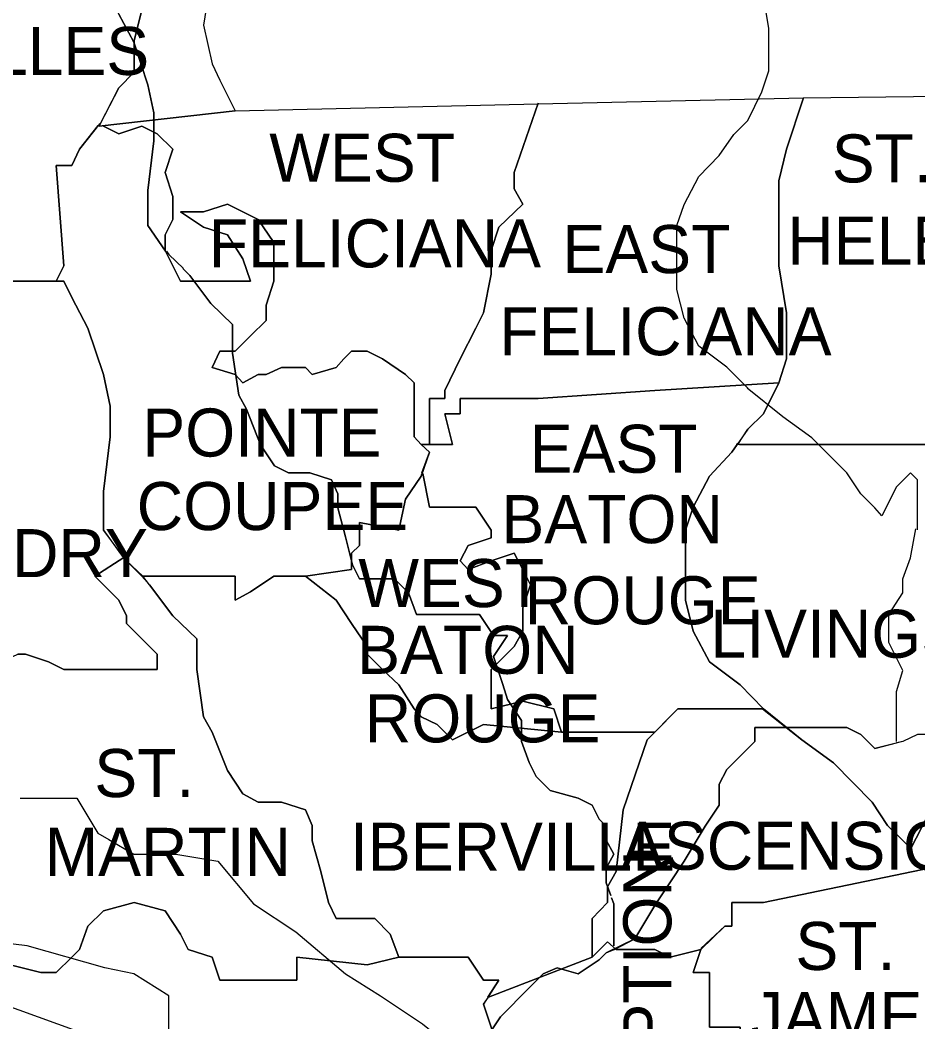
# Model space of a CAD drawing. Extents: x 0.19 to 2.82, y 0.04 to 1.79.
# Drawn here: x 2.3673 to 2.4634, y 1.4536 to 1.5609 of the extents above; entities that cross this region are included whole.
import ezdxf

# ---------------------------------------------------------------- set-up
doc = ezdxf.new("R2010")
doc.units = 0
for name, color, linetype in [('Dist02', 7, 'Continuous'), ('Dist03', 7, 'Continuous'), ('Dist61', 7, 'Continuous'), ('Dist62', 7, 'Continuous'), ('Standard Info', 7, 'Continuous')]:
    doc.layers.add(name, color=color, linetype=linetype)

msp = doc.modelspace()

# ---------------------------------------------------------------- linework, layer by layer
at = {"layer": 'Dist02'}
for points in [[(2.47174, 1.48442), (2.46715, 1.48442), (2.46565, 1.48292), (2.4649, 1.48442), (2.4634, 1.48442), (2.46182, 1.48367), (2.45882, 1.48292), (2.45732, 1.48442), (2.45582, 1.48517), (2.45357, 1.48517), (2.44599, 1.48517), (2.44599, 1.48367), (2.44299, 1.48067), (2.44215, 1.47908), (2.44215, 1.47683), (2.44065, 1.47458), (2.4384, 1.47083), (2.4369, 1.4685)], [(2.4369, 1.4685), (2.4354, 1.46625), (2.43315, 1.4625), (2.43007, 1.461), (2.42932, 1.46025), (2.42707, 1.45875), (2.42482, 1.45942), (2.42332, 1.45875), (2.42182, 1.45725), (2.41874, 1.45417), (2.41724, 1.45192), (2.41799, 1.44967), (2.41799, 1.44817), (2.42032, 1.44508), (2.42182, 1.44358), (2.42182, 1.44208), (2.42099, 1.44133), (2.41949, 1.43983), (2.41799, 1.43825), (2.41574, 1.43492)]]:
    msp.add_lwpolyline(points, dxfattribs=at)
at = {"layer": 'Dist03'}
for points in [[(2.3829, 1.53617), (2.38099, 1.53892), (2.38099, 1.54267), (2.38165, 1.548), (2.38165, 1.551), (2.38099, 1.554), (2.37949, 1.55858), (2.3779, 1.56158), (2.37715, 1.56308)], [(2.40974, 1.49725), (2.4089, 1.49958), (2.4074, 1.50108), (2.40365, 1.50108), (2.4029, 1.50258), (2.40215, 1.50558), (2.40132, 1.50867), (2.40132, 1.51017), (2.40065, 1.51167), (2.39832, 1.51242), (2.39607, 1.51242), (2.39457, 1.51317), (2.39307, 1.51542), (2.39157, 1.51925), (2.39074, 1.52075), (2.39007, 1.52525), (2.39007, 1.52833), (2.38774, 1.53058), (2.38549, 1.53358), (2.38474, 1.53433)], [(2.41899, 1.48975), (2.41799, 1.49275), (2.41949, 1.495), (2.41799, 1.495), (2.41649, 1.49725), (2.40974, 1.49725)], [(2.43057, 1.46717), (2.43007, 1.4685), (2.43007, 1.47008), (2.4309, 1.47158), (2.43007, 1.47308), (2.43007, 1.47458), (2.42932, 1.47533), (2.42857, 1.47683), (2.42707, 1.47758), (2.42407, 1.47842), (2.42257, 1.47992), (2.42182, 1.48142), (2.42099, 1.48367), (2.42099, 1.48592), (2.41949, 1.48817), (2.41899, 1.48975)], [(2.36732, 1.47758), (2.3734, 1.47758), (2.37565, 1.47383), (2.37682, 1.47317)], [(2.37682, 1.47317), (2.37949, 1.47158), (2.38399, 1.47158), (2.38849, 1.47083), (2.39232, 1.46625), (2.39682, 1.46325), (2.40215, 1.45875), (2.4059, 1.45642), (2.4104, 1.45342), (2.41499, 1.44967), (2.41649, 1.44817), (2.41724, 1.44358), (2.41499, 1.44133), (2.41424, 1.43675), (2.41574, 1.435)], [(2.4309, 1.46175), (2.4309, 1.46325), (2.4309, 1.46475), (2.4309, 1.46625), (2.43065, 1.46692)], [(2.36049, 1.45725), (2.36507, 1.45567), (2.3734, 1.45267), (2.37865, 1.45117), (2.38015, 1.45117), (2.38324, 1.45267), (2.38324, 1.45642), (2.37949, 1.45875), (2.3764, 1.45942), (2.36807, 1.46175), (2.36482, 1.46217)], [(2.41574, 1.435), (2.41799, 1.43825), (2.41949, 1.43983), (2.42099, 1.44133), (2.42182, 1.44208), (2.42182, 1.44358), (2.42032, 1.44508), (2.41799, 1.44817), (2.41799, 1.44967), (2.41724, 1.45192), (2.41874, 1.45417), (2.42182, 1.45725), (2.42332, 1.45875), (2.42482, 1.45942), (2.42707, 1.45875), (2.42932, 1.46025), (2.43007, 1.461), (2.43099, 1.46142)]]:
    msp.add_lwpolyline(points, dxfattribs=at)
at = {"layer": 'Dist61'}
for points in [[(2.44674, 1.55325), (2.44749, 1.5555), (2.44749, 1.56008), (2.44674, 1.56458), (2.44674, 1.56983), (2.44674, 1.57292), (2.44749, 1.57592), (2.44915, 1.581)], [(2.37715, 1.56308), (2.3779, 1.56158), (2.37949, 1.55858), (2.38099, 1.554), (2.38165, 1.551), (2.38165, 1.548), (2.38099, 1.54267), (2.38099, 1.53892), (2.3829, 1.53617)], [(2.44524, 1.5215), (2.44299, 1.52375), (2.43999, 1.526), (2.4384, 1.529), (2.43765, 1.53208), (2.43765, 1.53508), (2.43765, 1.53892), (2.4384, 1.54117), (2.43999, 1.54417), (2.44215, 1.54642), (2.44374, 1.54867), (2.44524, 1.55017), (2.44674, 1.55325)], [(2.38299, 1.53617), (2.38324, 1.53583), (2.38482, 1.53433)], [(2.38474, 1.53433), (2.38549, 1.53358), (2.38774, 1.53058), (2.39007, 1.52833), (2.39007, 1.52525), (2.39074, 1.52075), (2.39157, 1.51925), (2.39307, 1.51542), (2.39457, 1.51317), (2.39607, 1.51242), (2.39832, 1.51242), (2.40065, 1.51167), (2.40132, 1.51017), (2.40132, 1.50867), (2.40215, 1.50558), (2.4029, 1.50258), (2.40365, 1.50108), (2.4074, 1.50108), (2.4089, 1.49958), (2.40974, 1.49725)], [(2.4634, 1.50633), (2.4634, 1.51167), (2.46265, 1.51242), (2.46115, 1.51092), (2.45957, 1.50783), (2.45882, 1.50867), (2.45732, 1.51017), (2.45582, 1.51242), (2.45207, 1.51617), (2.44899, 1.51842), (2.44515, 1.5215)], [(2.46115, 1.48367), (2.46115, 1.48667), (2.46115, 1.489), (2.46182, 1.49125), (2.46032, 1.49425), (2.46032, 1.49575), (2.46032, 1.49725), (2.46182, 1.49958), (2.46182, 1.50108), (2.46265, 1.50333), (2.46324, 1.50642)], [(2.40974, 1.49725), (2.41649, 1.49725), (2.41799, 1.495), (2.41949, 1.495), (2.41799, 1.49275), (2.41899, 1.48975)], [(2.41899, 1.48975), (2.41949, 1.48817), (2.42099, 1.48592), (2.42099, 1.48367), (2.42182, 1.48142), (2.42257, 1.47992), (2.42407, 1.47842), (2.42707, 1.47758), (2.42857, 1.47683), (2.42932, 1.47533), (2.43007, 1.47458), (2.43007, 1.47308), (2.4309, 1.47158), (2.43007, 1.47008), (2.43007, 1.4685), (2.43057, 1.46717)], [(2.44524, 1.48292), (2.44599, 1.48367), (2.44599, 1.48517), (2.45357, 1.48517), (2.45582, 1.48517), (2.45732, 1.48442), (2.45882, 1.48292), (2.46115, 1.4835)], [(2.4309, 1.46133), (2.43315, 1.4625), (2.4354, 1.46625), (2.4369, 1.4685), (2.4384, 1.47083), (2.44065, 1.47458), (2.44215, 1.47683), (2.44215, 1.47908), (2.44299, 1.48067), (2.44524, 1.48292)], [(2.43065, 1.46692), (2.4309, 1.46625), (2.4309, 1.46475), (2.4309, 1.46325), (2.4309, 1.46175)]]:
    msp.add_lwpolyline(points, dxfattribs=at)
at = {"layer": 'Dist62'}
for points in [[(2.44674, 1.55325), (2.44749, 1.5555), (2.44749, 1.56008), (2.44674, 1.56458), (2.44674, 1.56983), (2.44674, 1.57292), (2.44749, 1.57592), (2.44915, 1.581)], [(2.44524, 1.5215), (2.44299, 1.52375), (2.43999, 1.526), (2.4384, 1.529), (2.43765, 1.53208), (2.43765, 1.53508), (2.43765, 1.53892), (2.4384, 1.54117), (2.43999, 1.54417), (2.44215, 1.54642), (2.44374, 1.54867), (2.44524, 1.55017), (2.44674, 1.55325)], [(2.4634, 1.50633), (2.4634, 1.51167), (2.46265, 1.51242), (2.46115, 1.51092), (2.45957, 1.50783), (2.45882, 1.50867), (2.45732, 1.51017), (2.45582, 1.51242), (2.45207, 1.51617), (2.44899, 1.51842), (2.44515, 1.5215)], [(2.46115, 1.48367), (2.46115, 1.48667), (2.46115, 1.489), (2.46182, 1.49125), (2.46032, 1.49425), (2.46032, 1.49575), (2.46032, 1.49725), (2.46182, 1.49958), (2.46182, 1.50108), (2.46265, 1.50333), (2.46324, 1.50642)], [(2.47174, 1.48442), (2.46715, 1.48442), (2.46565, 1.48292), (2.4649, 1.48442), (2.4634, 1.48442), (2.46182, 1.48367), (2.46115, 1.4835)]]:
    msp.add_lwpolyline(points, dxfattribs=at)
at = {"layer": 'Standard Info'}
for p, q in [((2.4228, 1.55204), (2.4228, 1.55195)), ((2.45121, 1.55259), (2.47101, 1.55286)), ((2.37201, 1.53297), (2.37119, 1.53297)), ((2.38045, 1.50135), (2.38035, 1.50135))]:
    msp.add_line(p, q, dxfattribs=at)
for points in [[(2.40685, 1.61694), (2.40446, 1.61281), (2.40281, 1.6086), (2.40281, 1.60447), (2.39951, 1.60117), (2.39695, 1.59613), (2.39695, 1.58779), (2.39612, 1.58449), (2.39447, 1.58119), (2.39365, 1.57862), (2.39117, 1.5745), (2.38952, 1.57285), (2.38787, 1.56625), (2.38695, 1.56038), (2.38787, 1.55626), (2.3887, 1.55451), (2.39035, 1.55121)], [(2.35111, 1.57908), (2.35295, 1.57789), (2.3546, 1.57532), (2.35542, 1.57367), (2.35707, 1.57202), (2.3579, 1.57037), (2.35955, 1.56955), (2.3612, 1.5712), (2.36037, 1.57285), (2.36202, 1.5745), (2.36624, 1.5745), (2.36871, 1.5712), (2.37119, 1.56863), (2.37531, 1.56698), (2.37788, 1.56698), (2.37953, 1.56625), (2.38118, 1.56451), (2.38035, 1.56203), (2.37953, 1.55873), (2.37953, 1.55534), (2.37788, 1.55369), (2.37586, 1.54975)], [(2.37577, 1.54956), (2.37788, 1.55369), (2.37953, 1.55534), (2.37953, 1.55873), (2.38035, 1.56203), (2.38118, 1.56451), (2.37953, 1.56625), (2.37788, 1.56698), (2.37531, 1.56698), (2.37119, 1.56863), (2.36871, 1.5712), (2.36798, 1.57211)], [(2.4228, 1.55204), (2.42023, 1.54461), (2.42023, 1.54287), (2.42115, 1.54122), (2.41858, 1.53875), (2.41775, 1.53627), (2.41775, 1.53371), (2.41693, 1.52958), (2.4161, 1.52793), (2.41445, 1.52463), (2.4128, 1.52124), (2.4128, 1.52041), (2.41115, 1.52041), (2.41115, 1.51794), (2.41115, 1.51546)], [(2.41115, 1.51546), (2.41115, 1.51794), (2.41115, 1.52041), (2.4128, 1.52041), (2.4128, 1.52124), (2.41445, 1.52463), (2.4161, 1.52793), (2.41693, 1.52958), (2.41775, 1.53371), (2.41775, 1.53627), (2.41858, 1.53875), (2.42115, 1.54122), (2.42023, 1.54287), (2.42023, 1.54461), (2.4228, 1.55204)], [(2.4228, 1.55195), (2.45121, 1.55259)], [(2.45121, 1.55259), (2.44938, 1.54709), (2.44855, 1.5437), (2.44855, 1.5404), (2.44855, 1.53462), (2.44938, 1.52958), (2.44938, 1.52463), (2.44855, 1.52206)], [(2.44855, 1.52206), (2.44938, 1.52463), (2.44938, 1.52958), (2.44855, 1.53462), (2.44855, 1.5404), (2.44855, 1.5437), (2.44938, 1.54709), (2.45121, 1.55259)], [(2.39035, 1.55121), (2.37577, 1.54956)], [(2.37577, 1.54956), (2.39035, 1.55121)], [(2.39035, 1.55121), (2.4228, 1.55195)], [(2.37586, 1.54984), (2.37366, 1.54709), (2.37284, 1.54535), (2.37119, 1.54535)], [(2.37119, 1.54535), (2.37284, 1.54535), (2.37366, 1.54709), (2.37568, 1.54966)], [(2.38365, 1.54205), (2.38283, 1.54461), (2.38365, 1.54709), (2.382, 1.54874), (2.38035, 1.54956), (2.37788, 1.54874), (2.37623, 1.54956)], [(2.37623, 1.54956), (2.37788, 1.54874), (2.38035, 1.54956), (2.382, 1.54874), (2.38365, 1.54709), (2.38283, 1.54461), (2.38365, 1.54205)], [(2.37119, 1.54535), (2.37201, 1.53462), (2.37119, 1.53297)], [(2.37119, 1.53297), (2.37201, 1.53462), (2.37119, 1.54535)], [(2.37119, 1.53297), (2.33709, 1.53297), (2.33709, 1.53792), (2.33544, 1.53957), (2.33379, 1.54122), (2.33379, 1.5437)], [(2.38448, 1.5404), (2.38695, 1.53875), (2.38952, 1.53792), (2.39117, 1.53536), (2.392, 1.53297), (2.39035, 1.53297), (2.38622, 1.53297), (2.38448, 1.53297), (2.38365, 1.53462), (2.38283, 1.53627), (2.38283, 1.53792), (2.38365, 1.53957), (2.38365, 1.54205)], [(2.38365, 1.54205), (2.38365, 1.53957), (2.38283, 1.53792), (2.38283, 1.53627), (2.38365, 1.53462), (2.38448, 1.53297), (2.38622, 1.53297), (2.39035, 1.53297), (2.392, 1.53297), (2.39117, 1.53536), (2.38952, 1.53792), (2.38695, 1.53875), (2.38448, 1.5404)], [(2.41024, 1.51546), (2.4095, 1.51629), (2.4095, 1.51876), (2.4095, 1.52206), (2.40859, 1.52298), (2.40611, 1.52463), (2.40446, 1.52546), (2.40281, 1.52546), (2.40199, 1.52463), (2.40116, 1.52371), (2.3986, 1.52298), (2.39786, 1.52371), (2.3953, 1.52371), (2.39365, 1.52298), (2.39282, 1.52298), (2.39117, 1.52206), (2.39035, 1.52298), (2.38787, 1.52371), (2.3887, 1.52546), (2.39035, 1.52546), (2.392, 1.52711), (2.39365, 1.52876), (2.39365, 1.53041), (2.39447, 1.53297), (2.39447, 1.5371), (2.39282, 1.53957), (2.38952, 1.54122), (2.38695, 1.5404), (2.38448, 1.5404)], [(2.38448, 1.5404), (2.38695, 1.5404), (2.38952, 1.54122), (2.39282, 1.53957), (2.39447, 1.5371), (2.39447, 1.53297), (2.39365, 1.53041), (2.39365, 1.52876), (2.392, 1.52711), (2.39035, 1.52546), (2.3887, 1.52546), (2.38787, 1.52371), (2.39035, 1.52298), (2.39117, 1.52206), (2.39282, 1.52298), (2.39365, 1.52298), (2.3953, 1.52371), (2.39786, 1.52371), (2.3986, 1.52298), (2.40116, 1.52371), (2.40199, 1.52463), (2.40281, 1.52546), (2.40446, 1.52546), (2.40611, 1.52463), (2.40859, 1.52298), (2.4095, 1.52206), (2.4095, 1.51876), (2.4095, 1.51629), (2.41024, 1.51546), (2.41115, 1.51464), (2.41024, 1.51207), (2.40859, 1.5096), (2.40785, 1.5063), (2.40364, 1.50712), (2.40364, 1.50465), (2.40281, 1.50382), (2.40281, 1.50208), (2.39786, 1.50135)], [(2.33874, 1.53297), (2.37201, 1.53297)], [(2.37201, 1.53297), (2.37284, 1.53123), (2.37458, 1.52793), (2.37623, 1.52298), (2.37696, 1.51959), (2.37696, 1.51629), (2.37623, 1.51042), (2.37623, 1.5063), (2.37834, 1.50336)], [(2.38035, 1.50135), (2.3787, 1.503), (2.37623, 1.5063), (2.37623, 1.51042), (2.37696, 1.51629), (2.37696, 1.51959), (2.37623, 1.52298), (2.37458, 1.52793), (2.37284, 1.53123), (2.37201, 1.53297)], [(2.41024, 1.51546), (2.41363, 1.51546), (2.4128, 1.51876), (2.41445, 1.51876), (2.41445, 1.52041), (2.4228, 1.52041), (2.43526, 1.52124), (2.44855, 1.52206)], [(2.44855, 1.52206), (2.43526, 1.52124), (2.4228, 1.52041), (2.41445, 1.52041), (2.41445, 1.51876), (2.4128, 1.51876), (2.41363, 1.51546), (2.41115, 1.51546)], [(2.44855, 1.52206), (2.4469, 1.51876), (2.44525, 1.51711), (2.44351, 1.51464), (2.44113, 1.51207), (2.43939, 1.50877), (2.43856, 1.5063), (2.43856, 1.50208), (2.43856, 1.49878), (2.43939, 1.49548), (2.44113, 1.49218), (2.44443, 1.48971), (2.4469, 1.48714)], [(2.44415, 1.51546), (2.44525, 1.51711), (2.4469, 1.51876), (2.44855, 1.52206)], [(2.4712, 1.51684), (2.4657, 1.51546), (2.44397, 1.51546)], [(2.44434, 1.51546), (2.46606, 1.51546), (2.47156, 1.51684)], [(2.44434, 1.51546), (2.46606, 1.51546), (2.47156, 1.51684)], [(2.46606, 1.47715), (2.46441, 1.4755), (2.46267, 1.4722), (2.46185, 1.47302), (2.4602, 1.47467), (2.45855, 1.47715), (2.45442, 1.48136), (2.45103, 1.48384), (2.4469, 1.48714), (2.44443, 1.48971), (2.44113, 1.49218), (2.43939, 1.49548), (2.43856, 1.49878), (2.43856, 1.50208), (2.43856, 1.5063), (2.43939, 1.50877), (2.44113, 1.51207), (2.44351, 1.51464), (2.44415, 1.51556)], [(2.41115, 1.51546), (2.41024, 1.51546)], [(2.41033, 1.51244), (2.41115, 1.51464), (2.41024, 1.51546)], [(2.39786, 1.50135), (2.40281, 1.50208), (2.40281, 1.50382), (2.40364, 1.50465), (2.40364, 1.50712), (2.40785, 1.5063), (2.40859, 1.5096), (2.41024, 1.51207), (2.41033, 1.51235)], [(2.41042, 1.51235), (2.41115, 1.50877), (2.4161, 1.50877), (2.41775, 1.5063), (2.41775, 1.50547), (2.41528, 1.50465), (2.41445, 1.503), (2.41528, 1.50208), (2.41775, 1.503), (2.42023, 1.50382), (2.42115, 1.50208), (2.42197, 1.50043), (2.42115, 1.49796), (2.42115, 1.49548), (2.42023, 1.49383), (2.41775, 1.49136), (2.41775, 1.49044), (2.41775, 1.48879), (2.41775, 1.48714), (2.42115, 1.48796), (2.42445, 1.48714), (2.42527, 1.48466)], [(2.42527, 1.48466), (2.42445, 1.48714), (2.42115, 1.48796), (2.41775, 1.48714), (2.41775, 1.48879), (2.41775, 1.49044), (2.41775, 1.49136), (2.42023, 1.49383), (2.42115, 1.49548), (2.42115, 1.49796), (2.42197, 1.50043), (2.42115, 1.50208), (2.42023, 1.50382), (2.41775, 1.503), (2.41528, 1.50208), (2.41445, 1.503), (2.41528, 1.50465), (2.41775, 1.50547), (2.41775, 1.5063), (2.4161, 1.50877), (2.41115, 1.50877), (2.41042, 1.51235)], [(2.35597, 1.48906), (2.35707, 1.49136), (2.35872, 1.49218), (2.36037, 1.49136), (2.36202, 1.49044), (2.36532, 1.49218), (2.36706, 1.49301), (2.36789, 1.49301), (2.37036, 1.49218), (2.37201, 1.49136), (2.382, 1.49136), (2.382, 1.49301), (2.38118, 1.49383), (2.3787, 1.49631), (2.3787, 1.49713), (2.37788, 1.49878), (2.37531, 1.50135), (2.37843, 1.50336)], [(2.37843, 1.50336), (2.37531, 1.50135), (2.37788, 1.49878), (2.3787, 1.49713), (2.3787, 1.49631), (2.38118, 1.49383), (2.382, 1.49301), (2.382, 1.49136), (2.37201, 1.49136), (2.37036, 1.49218), (2.36789, 1.49301), (2.36706, 1.49301)], [(2.37843, 1.50336), (2.3787, 1.503), (2.38045, 1.50135)], [(2.38035, 1.50135), (2.38118, 1.50043), (2.38365, 1.49713), (2.38622, 1.49466), (2.38622, 1.49136), (2.38695, 1.48631), (2.38787, 1.48466), (2.38952, 1.48054), (2.39117, 1.47806), (2.39282, 1.47715), (2.3953, 1.47715), (2.39786, 1.47632), (2.3986, 1.47467), (2.3986, 1.47302), (2.39951, 1.46972), (2.40034, 1.46642), (2.40116, 1.46468), (2.40529, 1.46468), (2.40694, 1.46303), (2.40785, 1.46056)], [(2.39786, 1.50135), (2.39447, 1.50135), (2.392, 1.4997), (2.39035, 1.49878), (2.39035, 1.50135), (2.38035, 1.50135)], [(2.39786, 1.50135), (2.39447, 1.50135), (2.392, 1.4997), (2.39035, 1.49878), (2.39035, 1.50135), (2.38035, 1.50135)], [(2.38035, 1.50135), (2.39035, 1.50135), (2.39035, 1.49878), (2.392, 1.4997), (2.39447, 1.50135), (2.39786, 1.50135)], [(2.41739, 1.45625), (2.41858, 1.45808), (2.41693, 1.45808), (2.41528, 1.46056), (2.40785, 1.46056), (2.40694, 1.46303), (2.40529, 1.46468), (2.40116, 1.46468), (2.40034, 1.46642), (2.39951, 1.46972), (2.3986, 1.47302), (2.3986, 1.47467), (2.39786, 1.47632), (2.3953, 1.47715), (2.39282, 1.47715), (2.39117, 1.47806), (2.38952, 1.48054), (2.38787, 1.48466), (2.38695, 1.48631), (2.38622, 1.49136), (2.38622, 1.49466), (2.38365, 1.49713), (2.38118, 1.50043), (2.38045, 1.50135)], [(2.39786, 1.50135), (2.40116, 1.49878), (2.40281, 1.49631), (2.40446, 1.49383), (2.40446, 1.49301), (2.40611, 1.49136), (2.40785, 1.48971), (2.4095, 1.48714), (2.41024, 1.48631), (2.41198, 1.48549), (2.41363, 1.48384), (2.41693, 1.48549), (2.42527, 1.48466)], [(2.43526, 1.48466), (2.42527, 1.48466), (2.41693, 1.48549), (2.41363, 1.48384), (2.41198, 1.48549), (2.41024, 1.48631), (2.4095, 1.48714), (2.40785, 1.48971), (2.40611, 1.49136), (2.40446, 1.49301), (2.40446, 1.49383), (2.40281, 1.49631), (2.40116, 1.49878), (2.39786, 1.50135)], [(2.39786, 1.50135), (2.40116, 1.49878), (2.40281, 1.49631), (2.40446, 1.49383), (2.40446, 1.49301), (2.40611, 1.49136), (2.40785, 1.48971), (2.4095, 1.48714), (2.41024, 1.48631), (2.41198, 1.48549), (2.41363, 1.48384), (2.41693, 1.48549), (2.42527, 1.48466), (2.43526, 1.48466)], [(2.42857, 1.46056), (2.42857, 1.46303), (2.42857, 1.46468), (2.43022, 1.46642), (2.43022, 1.46807), (2.43114, 1.46972), (2.43187, 1.47632), (2.43444, 1.48384), (2.43774, 1.48714), (2.4469, 1.48714)], [(2.4469, 1.48714), (2.43774, 1.48714), (2.43526, 1.48466)], [(2.44681, 1.48714), (2.45103, 1.48384), (2.45442, 1.48136), (2.45855, 1.47715), (2.4602, 1.47467), (2.46185, 1.47302), (2.46267, 1.4722), (2.46441, 1.4755), (2.46606, 1.47715), (2.46689, 1.47632), (2.46689, 1.47055)], [(2.43526, 1.48466), (2.42527, 1.48466)], [(2.43526, 1.48466), (2.43444, 1.48384), (2.43187, 1.47632), (2.43114, 1.46972), (2.43022, 1.46807), (2.43022, 1.46642), (2.42857, 1.46468), (2.42857, 1.46303), (2.42857, 1.46056)], [(2.46689, 1.47055), (2.4469, 1.46642), (2.44351, 1.46642), (2.44351, 1.46386), (2.44278, 1.46386), (2.44021, 1.46138), (2.43691, 1.46056), (2.43526, 1.46138), (2.43444, 1.46138), (2.43279, 1.46138), (2.43114, 1.46138), (2.43022, 1.46221), (2.42857, 1.46056)], [(2.44021, 1.46147), (2.44278, 1.46386), (2.44351, 1.46386), (2.44351, 1.46642), (2.4469, 1.46642), (2.46689, 1.47055)], [(2.35918, 1.46056), (2.36285, 1.46056), (2.36624, 1.45973), (2.36954, 1.45891), (2.37119, 1.45891), (2.37284, 1.46056), (2.37366, 1.46138), (2.37458, 1.46386), (2.37623, 1.46551), (2.37953, 1.46642), (2.38283, 1.46551), (2.38448, 1.46303), (2.3853, 1.46138), (2.38787, 1.46056), (2.3887, 1.45808), (2.39695, 1.45808), (2.39695, 1.46056), (2.40446, 1.45973), (2.40785, 1.46056)], [(2.40785, 1.46056), (2.40446, 1.45973), (2.39695, 1.46056), (2.39695, 1.45808), (2.3887, 1.45808), (2.38787, 1.46056), (2.3853, 1.46138), (2.38448, 1.46303), (2.38283, 1.46551), (2.37953, 1.46642), (2.37623, 1.46551), (2.37458, 1.46386), (2.37366, 1.46138), (2.37284, 1.46056), (2.37119, 1.45891), (2.36954, 1.45891), (2.36624, 1.45973), (2.36285, 1.46056), (2.35918, 1.46056)], [(2.42857, 1.46056), (2.43022, 1.46221), (2.43114, 1.46138), (2.43279, 1.46138), (2.43444, 1.46138), (2.43526, 1.46138), (2.43691, 1.46056), (2.44021, 1.46138)], [(2.44021, 1.46138), (2.43939, 1.45891), (2.44113, 1.45891), (2.44113, 1.45304), (2.44443, 1.45304), (2.44443, 1.44891), (2.4469, 1.44891), (2.4469, 1.44479)], [(2.4469, 1.44479), (2.4469, 1.44891), (2.44443, 1.44891), (2.44443, 1.45304), (2.44113, 1.45304), (2.44113, 1.45891), (2.43939, 1.45891), (2.44021, 1.46138)], [(2.40785, 1.46056), (2.41528, 1.46056), (2.41693, 1.45808), (2.41858, 1.45808), (2.41693, 1.45551), (2.41803, 1.45221)], [(2.41748, 1.45625), (2.42857, 1.46056)], [(2.42857, 1.46056), (2.41748, 1.45625)], [(2.43114, 1.42151), (2.43114, 1.42481), (2.43114, 1.42646), (2.43022, 1.42893), (2.43022, 1.43058), (2.43114, 1.43223), (2.43022, 1.43388), (2.43022, 1.43553), (2.4294, 1.43645), (2.42857, 1.4381), (2.42692, 1.43892), (2.42362, 1.43975), (2.42197, 1.4414), (2.42115, 1.44305), (2.42023, 1.44552), (2.42023, 1.44809), (2.41858, 1.45056), (2.41775, 1.45304), (2.41693, 1.45551), (2.41748, 1.45625)]]:
    msp.add_lwpolyline(points, dxfattribs=at)

# ---------------------------------------------------------------- texts
for s, height, p in [('AVOYELLES', 0.005147, (2.34058, 1.55506)), ('WEST', 0.005147, (2.394, 1.54361)), ('ST.', 0.005147, (2.45422, 1.54354)), ('FELICIANA', 0.005147, (2.38752, 1.53444)), ('HELENA', 0.005146, (2.44946, 1.53474)), ('EAST', 0.005147, (2.42539, 1.53383)), ('FELICIANA', 0.005147, (2.41863, 1.52503)), ('POINTE', 0.005146, (2.3804, 1.51418)), ('EAST', 0.005147, (2.42188, 1.51244)), ('COUPEE', 0.005147, (2.3798, 1.5063)), ('BATON', 0.005147, (2.41885, 1.5049)), ('ST. LANDRY', 0.005147, (2.34045, 1.50126)), ('WEST', 0.005147, (2.40353, 1.49805)), ('ROUGE', 0.005147, (2.42136, 1.49621)), ('LIVINGSTON', 0.005147, (2.44124, 1.49262)), ('BATON', 0.005147, (2.40341, 1.4909)), ('ROUGE', 0.005146, (2.40423, 1.48356)), ('ST.', 0.005147, (2.37526, 1.4777)), ('IBERVILLE', 0.005147, (2.40264, 1.46981)), ('ASCENSION', 0.005147, (2.43165, 1.46991)), ('MARTIN', 0.005147, (2.36994, 1.46926)), ('ST.', 0.005147, (2.45033, 1.45918)), ('JAMES', 0.005147, (2.44556, 1.45166))]:
    msp.add_text(s, height=height, dxfattribs=at).set_placement(p)
msp.add_text('ASSUMPTION', height=0.005147, rotation=90.01, dxfattribs=at).set_placement((2.43705, 1.42651))

doc.saveas('drawing.dxf')
